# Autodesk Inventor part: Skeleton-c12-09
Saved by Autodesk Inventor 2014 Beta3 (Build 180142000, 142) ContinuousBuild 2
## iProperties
Created: 2011-01
Part Number: Skeleton-c12-09
Material: Generic
Document SubType Name: Modeling
Designer: Thom Tremblay
Density: 1 g/cm^3
Appearance: Generic
_SkeletonDoc: Frame Skeleton File
_Version: 15.0.0
Author: Thom Tremblay
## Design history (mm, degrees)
sketch "Reference Skeleton"
  geometry: L1 through (325.691, 1070.446) direction (1, 0); L2 through (404.523, 1164.395) direction (1, 0); 34 other entities
  constraints: 10 horizontal
